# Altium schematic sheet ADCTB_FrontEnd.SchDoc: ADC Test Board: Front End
size B; Organization: LIGO Laboratory; Address1: California Institute of Technology; Address2: Massachusetts Institute of Technology; Address3: Joshua R. Myers; DocumentNumber: D060535; Revision: 0; SheetNumber: 3; SheetTotal: 9; PageSetup: Record=PageOptions|CenterHorizontal=True|CenterVertical=True|PrintScale=1.12|XCorrection=1.00|YCorrection=1.00|PrintKind=2|BorderSize=5000000|LeftOffset=0|BottomOffset=0|Orientation=2|PaperLength=1000|PaperWidth=1000|Scale=100|PaperSource=7|PrintQuality=-4|MediaType=1|DitherType=10|PaperKind=Tabloid|PrintScaleMode=1
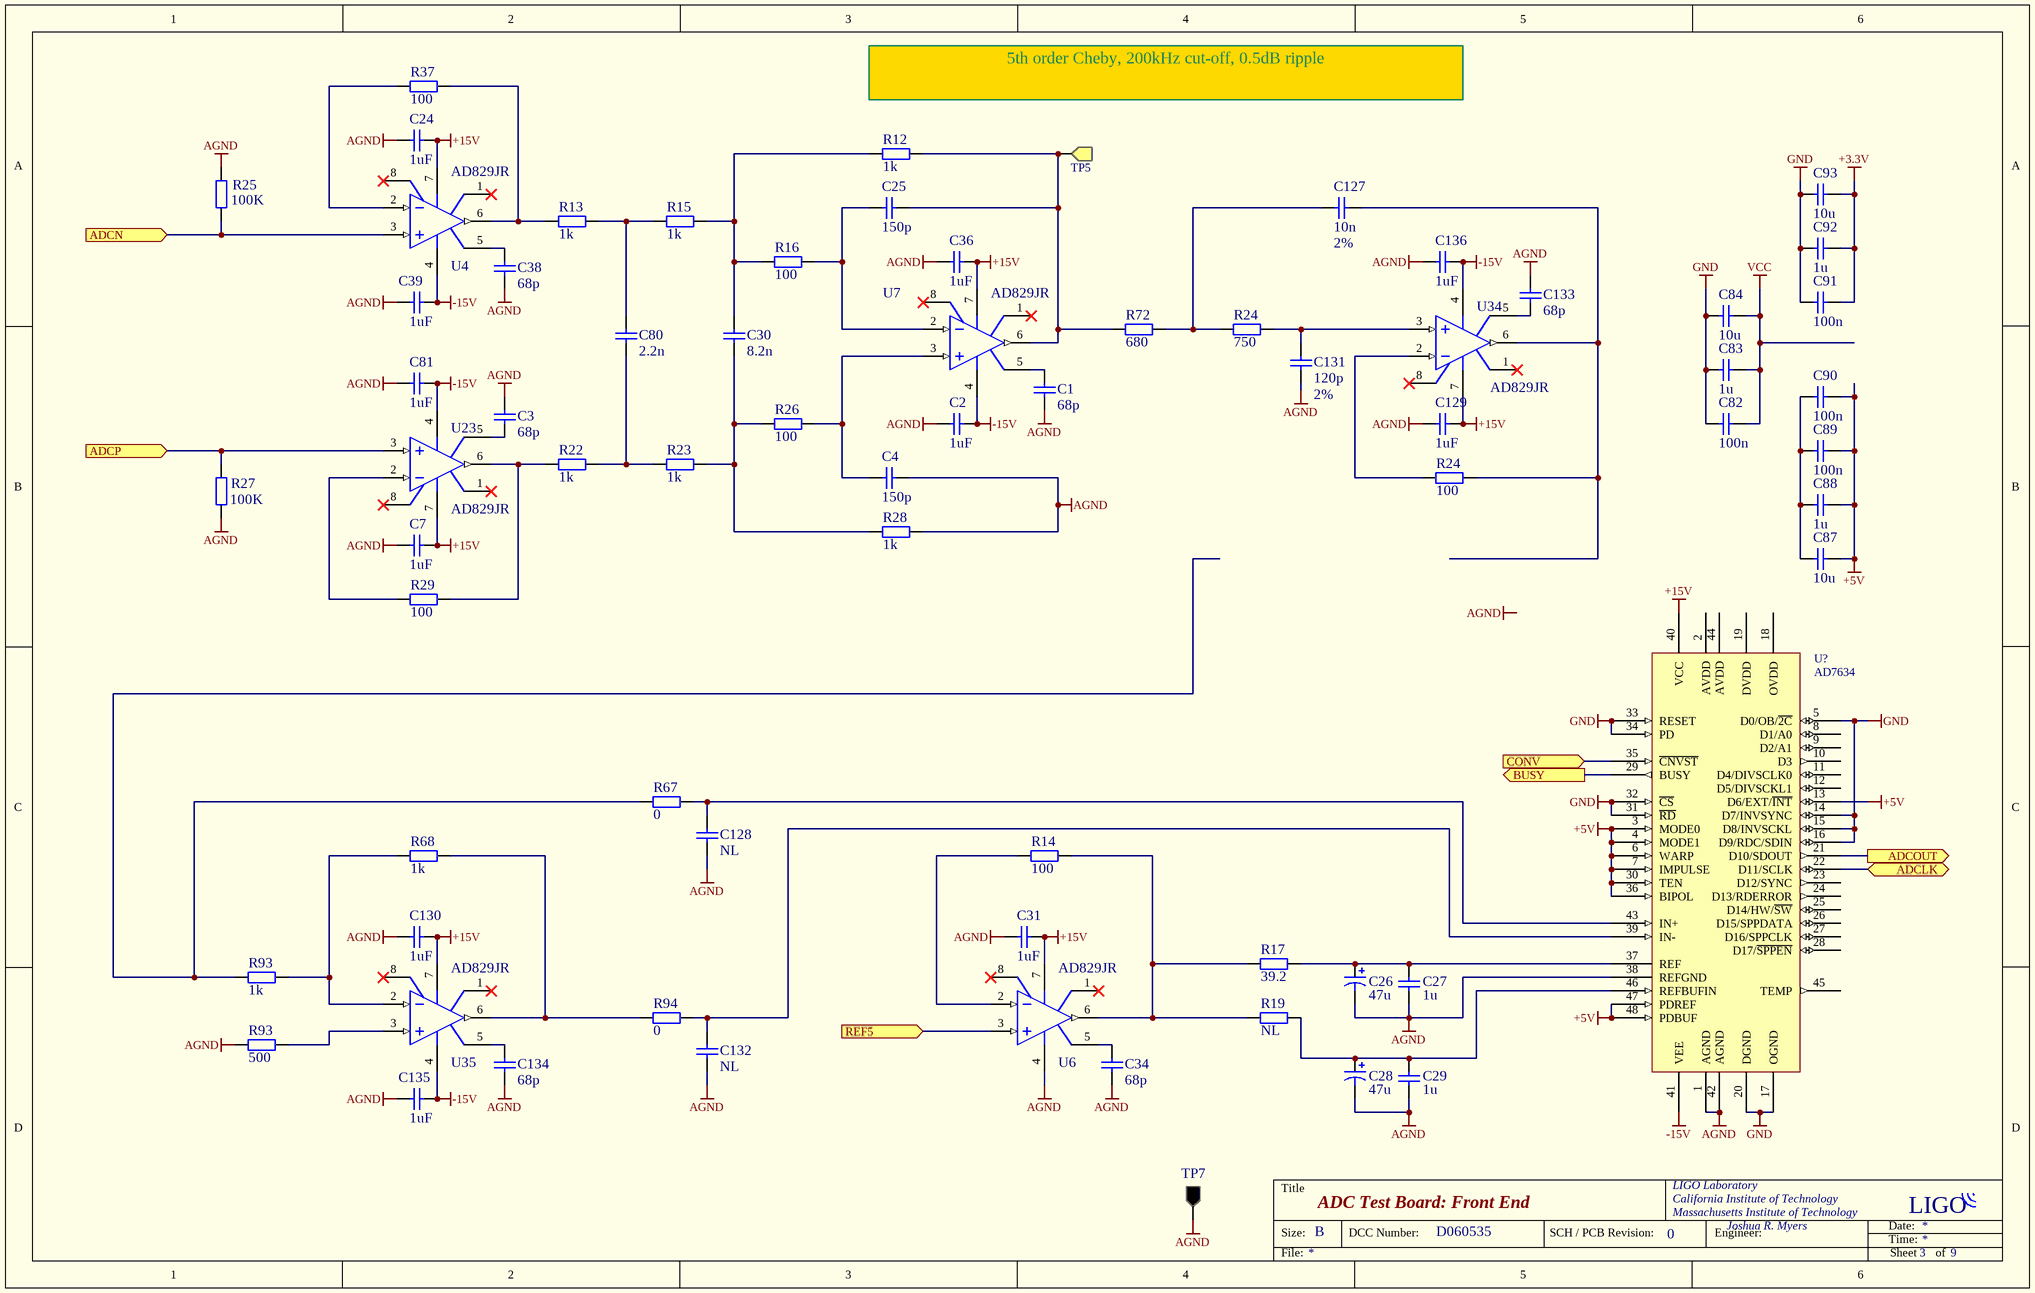
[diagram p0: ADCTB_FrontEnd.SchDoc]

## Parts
(Parts that share a designator on the sheet are numbered #1, #2 ... from top to bottom, then left to right.)
C1  68p  [CC2012-0805]
C2  1uF  [CC2012-0805]
C3  68p  [CC2012-0805]
C4  150p  [CC2012-0805]
C7  1uF  [CC2012-0805]
C24  1uF  [CC2012-0805]
C25  150p  [CC2012-0805]
C26  47u  [CC2012-0805]
C27  1u  [CC2012-0805]
C28  47u  [CC2012-0805]
C29  1u  [CC2012-0805]
C30  8.2n  [CC2012-0805]
C31  1uF  [CC2012-0805]
C34  68p  [CC2012-0805]
C36  1uF  [CC2012-0805]
C38  68p  [CC2012-0805]
C39  1uF  [CC2012-0805]
C80  2.2n  [CC2012-0805]
C81  1uF  [CC2012-0805]
C82  100n  [CC2012-0805]
C83  1u  [CC2012-0805]
C84  10u  [CC2012-0805]
C87  10u  [CC2012-0805]
C88  1u  [CC2012-0805]
C89  100n  [CC2012-0805]
C90  100n  [CC2012-0805]
C91  100n  [CC2012-0805]
C92  1u  [CC2012-0805]
C93  10u  [CC2012-0805]
C127  Tolerance: 2%  [CC2012-0805]  (hidden comment: 10n)
C128  NL  [CC2012-0805]
C129  1uF  [CC2012-0805]
C130  1uF  [CC2012-0805]
C131  Tolerance: 2%  [CC2012-0805]  (hidden comment: 120p)
C132  NL  [CC2012-0805]
C133  68p  [CC2012-0805]
C134  68p  [CC2012-0805]
C135  1uF  [CC2012-0805]
C136  1uF  [CC2012-0805]
R12  1k  [CR2012-0805]
R13  1k  [CR2012-0805]
R14  100  [CR2012-0805]
R15  1k  [CR2012-0805]
R16  100  [CR2012-0805]
R17  39.2  [CR2012-0805]
R19  NL  [CR2012-0805]
R22  1k  [CR2012-0805]
R23  1k  [CR2012-0805]
R24#1  750  [CR2012-0805]
R24#2  100  [CR2012-0805]
R25  100K  [CR2012-0805]
R26  100  [CR2012-0805]
R27  100K  [CR2012-0805]
R28  1k  [CR2012-0805]
R29  100  [CR2012-0805]
R37  100  [CR2012-0805]
R67  0  [CR2012-0805]
R68  1k  [CR2012-0805]
R72  680  [CR2012-0805]
R93#1  1k  [CR2012-0805]
R93#2  500  [CR2012-0805]
R94  0  [CR2012-0805]
TP5  Testpoint  [TP1]  (value not drawn)
TP7  Testpoint  [TP1]  (value not drawn)
U4  AD829JR  [R-8D_N]
U6  AD829JR  [R-8D_N]
U7  AD829JR  [R-8D_N]
U23  AD829JR  [R-8D_N]
U34  AD829JR  [R-8D_N]
U35  AD829JR  [R-8D_N]
U?  AD7634  [LQFP7x7-G48/N]

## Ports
ADCLK (bidir), ADCN (in), ADCOUT (out), ADCP (in), BUSY (out), CONV (in), REF5 (in)

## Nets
+3.3V: C91.2 C92.2 C93.2
+5V: C87.2 C88.2 C89.2 C90.2 U?.3(MODE0) U?.4(MODE1) U?.6(WARP) U?.7(IMPULSE) U?.13(D6/EXT/~{INT}) U?.30(TEN) U?.36(BIPOL) U?.47(PDREF) U?.48(PDBUF)
+15V: C7.1 C24.1 C31.1 C36.1 C129.1 C130.1 U4.7(V+) U6.7(V+) U7.7(V+) U23.7(V+) U34.7(V+) U35.7(V+) U?.40(VCC)
-15V: C2.1 C39.1 C81.1 C135.1 C136.1 U4.4(V-) U7.4(V-) U23.4(V-) U34.4(V-) U35.4(V-) U?.41(VEE)
AGND: C1.2 C2.2 C3.2 C4.1 C7.2 C24.2 C26.2 C27.2 C28.2 C29.2 C31.2 C34.2 C36.2 C38.2 C39.2 C81.2 C128.2 C129.2 C130.2 C131.2 C132.2 C133.2 C134.2 C135.2 C136.2 R25.2 R27.2 R28.2 R93#2.2 TP7.1 U6.4(V-) U?.1(AGND) U?.38(REFGND) U?.42(AGND)
GND: C82.1 C83.1 C84.1 C91.1 C92.1 C93.1 U?.5(D0/OB/~{2C}) U?.14(D7/INVSYNC) U?.15(D8/INVSCKL) U?.16(D9/RDC/SDIN) U?.17(OGND) U?.20(DGND) U?.31(~{RD}) U?.32(~{CS}) U?.33(RESET) U?.34(PD)
VCC: C82.2 C83.2 C84.2
ADCLK: U?.22(D11/SCLK) ; port ADCLK
ADCN: R25.1 U4.3(IN+) ; port ADCN
ADCOUT: U?.21(D10/SDOUT) ; port ADCOUT
ADCP: R27.1 U23.3(IN+) ; port ADCP
BUSY: U?.29(BUSY) ; port BUSY
CONV: U?.35(~{CNVST}) ; port CONV
REF5: U6.3(IN+) ; port REF5
NetC1_1: C1.1 U7.5(C_COMP)
NetC3_1: C3.1 U23.5(C_COMP)
NetC4_2: C4.2 R26.2 U7.3(IN+)
NetC25_1: C25.1 R12.2 R72.1 TP5.1 U7.6(OUT)
NetC25_2: C25.2 R16.2 U7.2(IN-)
NetC26_1: C26.1 C27.1 R17.1 U?.37(REF)
NetC28_1: C28.1 C29.1 R19.1 U?.46(REFBUFIN)
NetC30_1: C30.1 R12.1 R15.2 R16.1
NetC30_2: C30.2 R23.2 R26.1 R28.1
NetC34_1: C34.1 U6.5(C_COMP)
NetC38_1: C38.1 U4.5(C_COMP)
NetC80_1: C80.1 R13.2 R15.1
NetC80_2: C80.2 R22.2 R23.1
NetC87_1: C87.1 C88.1 C89.1 C90.1
NetC127_1: C127.1 R24#2.2 U34.6(OUT)
NetC127_2: C127.2 R24#1.1 R72.2
NetC128_1: C128.1 R67.1 U?.43(IN+)
NetC131_1: C131.1 R24#1.2 U34.3(IN+)
NetC132_1: C132.1 R94.1 U?.39(IN-)
NetC133_1: C133.1 U34.5(C_COMP)
NetC134_1: C134.1 U35.5(C_COMP)
NetR13_1: R13.1 R37.2 U4.6(OUT)
NetR14_1: R14.1 R17.2 R19.2 U6.6(OUT)
NetR14_2: R14.2 U6.2(IN-)
NetR22_1: R22.1 R29.2 U23.6(OUT)
NetR24#2_1: R24#2.1 U34.2(IN-)
NetR29_1: R29.1 U23.2(IN-)
NetR37_1: R37.1 U4.2(IN-)
NetR67_2: R67.2 R93#1.2
NetR68_1: R68.1 R94.2 U35.6(OUT)
NetR68_2: R68.2 R93#1.1 U35.2(IN-)
NetR93#2_1: R93#2.1 U35.3(IN+)

Not connected (* = marked no-connect by the designer): U4 1(OS_NUL)* 8(OS_NUL)*; U6 1(OS_NUL)* 8(OS_NUL)*; U7 1(OS_NUL)* 8(OS_NUL)*; U23 1(OS_NUL)* 8(OS_NUL)*; U34 1(OS_NUL)* 8(OS_NUL)*; U35 1(OS_NUL)* 8(OS_NUL)*; U? 2(AVDD) 8(D1/A0) 9(D2/A1) 10(D3) 11(D4/DIVSCLK0) 12(D5/DIVSCKL1) 18(OVDD) 19(DVDD) 23(D12/SYNC) 24(D13/RDERROR) 25(D14/HW/~{SW}) 26(D15/SPPDATA) 27(D16/SPPCLK) 28(D17/~{SPPEN}) 44(AVDD) 45(TEMP)

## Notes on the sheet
- 5th order Cheby, 200kHz cut-off, 0.5dB ripple
- Labels drawn without touching a wire or pin: AGND

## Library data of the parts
C1 C3 C4 C25 C30 C34 C38 C80 C133 C134 = Cap Semi: Capacitor (Semiconductor SIM Model); Part Number: 311-1109-1-ND
C2 C7 C24 C27 C29 C31 C36 C39 C81 C129 C130 C135 C136 = Cap Semi: Capacitor (Semiconductor SIM Model); Part Number: PCC2319CT-ND
C26 C28 = T494D: Solid Tantalum Chip Capacitor, Standard T494 Series - Low ESR, Industrial Grade
C82 C89-C91 = Cap Semi: Capacitor (Semiconductor SIM Model); Part Number: PCC2363CT-ND
C83 C88 C92 = Cap Semi: Capacitor (Semiconductor SIM Model); Part Number: PCC1893CT-ND
C84 C87 C93 = Cap Semi: Capacitor (Semiconductor SIM Model); Part Number: 490-1709-1-ND
C127 = Cap Semi: Capacitor (Semiconductor SIM Model); Part Number: 311-1105-1-ND
C128 C132 = Cap Semi: Capacitor (Semiconductor SIM Model); Part Number: 478-1392-1-ND; Tolerance: 5%
C131 = Cap Semi: Capacitor (Semiconductor SIM Model); Part Number: 490-1642-1-ND
R12 R13 R15 R16 R22 R23 R25-R29 R37 = Res2: Resistor; Part Number: 311-100KCRCT-ND; Tolerance: 0.05%
R14 = Res2: Resistor; Part Number: 311-100CRCT-ND; Tolerance: 0.05%
R17 R67 R94 = Res2: Resistor; Part Number: 311-39.2CRCT-ND; Tolerance: 0.05%
R19 = Res2: Resistor; Tolerance: 0.05%
R24#1 R24#2 = Res2: Resistor; Part Number: RR12P649BCT-ND; Tolerance: 0.05%
R68 R93#1 R93#2 = Res2: Resistor; Part Number: RR12P604BCT-ND; Tolerance: 0.05%
R72 = Res2: Resistor; Part Number: RR12P1.3KBCT-ND; Tolerance: 0.05%
TP5 = TP_SIGNAL: Testpoint, yellow; Part Number: 5009K-ND
TP7 = TP_GND: Part Number: 5006K-ND
U4 U6 U7 U23 U34 U35 = AD829JR: High-Speed, Low-Noise Video Operational Amplifier; Part Number: AD829JR-ND; PackageDocument: 1998
U? = AD7634BST: 18 bit SAR ADC, 670kSPS, 10V bipolar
